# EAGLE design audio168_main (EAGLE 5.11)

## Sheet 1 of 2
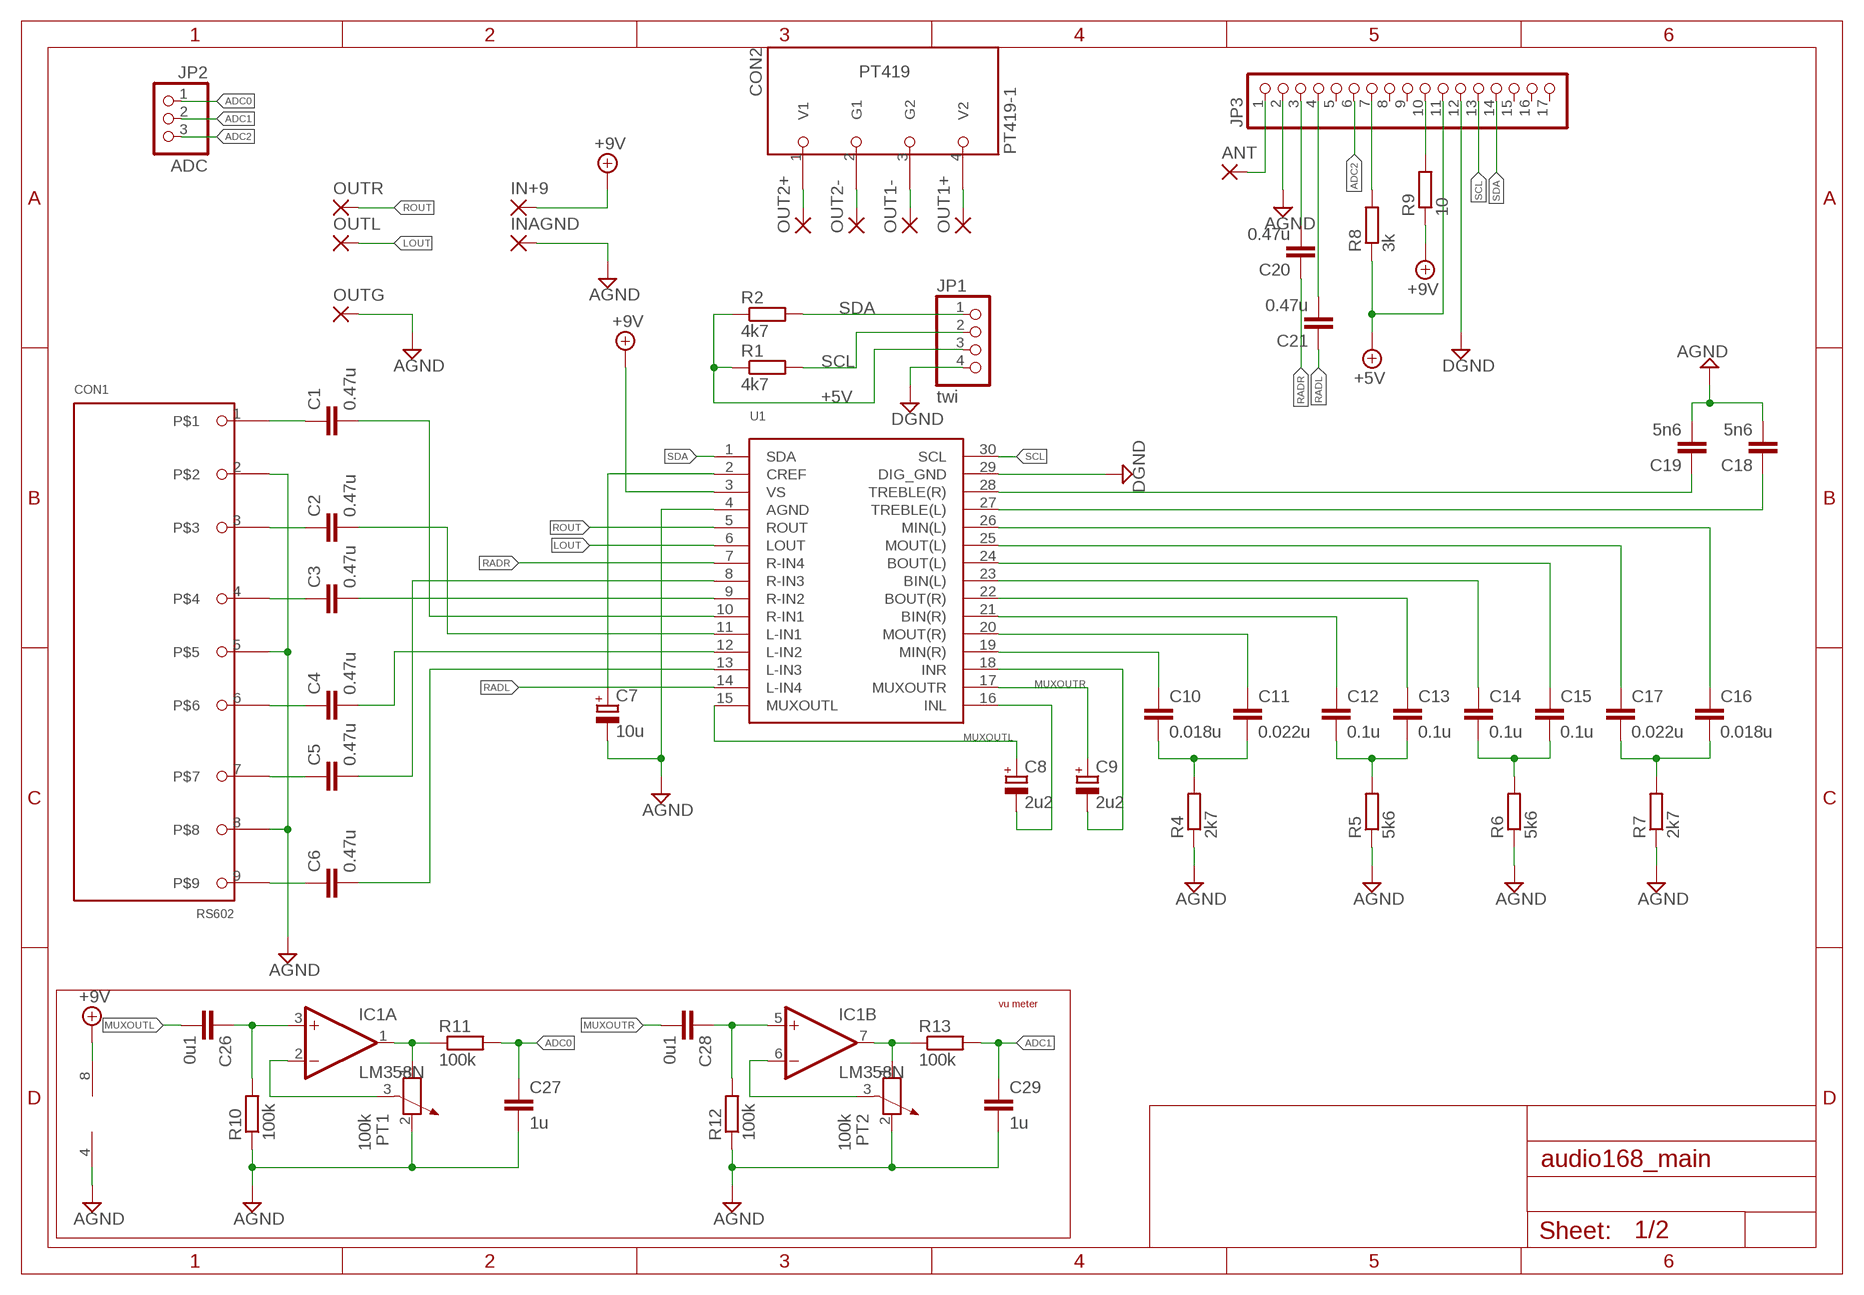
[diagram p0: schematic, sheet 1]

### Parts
ANT  2,54/0,8  [2,54/0,8]
C1  0.47u  C-EU050-055X075  [C050-055X075]
C2  0.47u  C-EU050-055X075  [C050-055X075]
C3  0.47u  C-EU050-055X075  [C050-055X075]
C4  0.47u  C-EU050-055X075  [C050-055X075]
C5  0.47u  C-EU050-055X075  [C050-055X075]
C6  0.47u  C-EU050-055X075  [C050-055X075]
C7  10u  CPOL-EUE5-4  [E5-4]
C8  2u2  CPOL-EUE2.5-6  [E2,5-6]
C9  2u2  CPOL-EUE2.5-6  [E2,5-6]
C10  0.018u  C-EU050-055X075  [C050-055X075]
C11  0.022u  C-EU050-055X075  [C050-055X075]
C12  0.1u  C-EU050-055X075  [C050-055X075]
C13  0.1u  C-EU050-055X075  [C050-055X075]
C14  0.1u  C-EU050-055X075  [C050-055X075]
C15  0.1u  C-EU050-055X075  [C050-055X075]
C16  0.018u  C-EU050-055X075  [C050-055X075]
C17  0.022u  C-EU050-055X075  [C050-055X075]
C18  5n6  C-EU050-055X075  [C050-055X075]
C19  5n6  C-EU050-055X075  [C050-055X075]
C20  0.47u  C-EU050-055X075  [C050-055X075]
C21  0.47u  C-EU050-055X075  [C050-055X075]
C26  0u1  C-EU050-055X075  [C050-055X075]
C27  1u  C-EU050-055X075  [C050-055X075]
C28  0u1  C-EU050-055X075  [C050-055X075]
C29  1u  C-EU050-055X075  [C050-055X075]
CON1  RS602  [RS602]
CON2  PT419-1  [PT419]
IC1  LM358N  [DIL08]
IN+9  2,54/0,8  [2,54/0,8]
INAGND  2,54/0,8  [2,54/0,8]
JP1  twi  PINHD-1X4  [1X04]
JP2  ADC  PINHD-1X3  [1X03]
JP3  PINHD-1X17  [1X17]
OUT1+  2,54/0,8  [2,54/0,8]
OUT1-  2,54/0,8  [2,54/0,8]
OUT2+  2,54/0,8  [2,54/0,8]
OUT2-  2,54/0,8  [2,54/0,8]
OUTG  2,54/0,8  [2,54/0,8]
OUTL  2,54/0,8  [2,54/0,8]
OUTR  2,54/0,8  [2,54/0,8]
PT1  100k  POTE  [PT-20]
PT2  100k  POTE  [PT-20]
R1  4k7  R-EU_0207/7  [0207/7]
R2  4k7  R-EU_0207/7  [0207/7]
R4  2k7  R-EU_0207/7  [0207/7]
R5  5k6  R-EU_0207/7  [0207/7]
R6  5k6  R-EU_0207/7  [0207/7]
R7  2k7  R-EU_0207/7  [0207/7]
R8  3k  R-EU_M1206  [M1206]
R9  10  R-EU_M1206  [M1206]
R10  100k  R-EU_M1206  [M1206]
R11  100k  R-EU_M1206  [M1206]
R12  100k  R-EU_M1206  [M1206]
R13  100k  R-EU_M1206  [M1206]
U1  TDA7439  [SDIP]

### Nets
+5V: JP1.3 JP3.11 R1.1 R2.1 R8.1
+9V: IC1.8(P:V+) IN+9.1(P) R9.1 U1.3(VS)
ADC0: C27.1 JP2.1 R11.2
ADC1: C29.1 JP2.2 R13.2
ADC2: JP2.3 JP3.6
AGND: C7.- C18.2 C19.2 C27.2 C29.2 CON1.2 CON1.5 CON1.8 IC1.4(P:V-) INAGND.1(P) JP3.2 OUTG.1(P) PT1.2 PT2.2 R4.1 R5.1 R6.1 R7.1 R10.1 R12.1 U1.4(AGND)
DGND: JP1.4 JP3.12 U1.29(DIG_GND)
LOUT: OUTL.1(P) U1.6(LOUT)
MUXOUTL: C8.+ C26.2 U1.15(MUXOUTL)
MUXOUTR: C9.+ C28.2 U1.17(MUXOUTR)
N$17: C1.2 U1.10(R-IN1)
N$18: C1.1 CON1.1
N$19: C2.1 CON1.3
N$20: C3.1 CON1.4
N$21: C4.1 CON1.6
N$22: C5.1 CON1.7
N$23: C6.1 CON1.9
N$24: C2.2 U1.11(L-IN1)
N$25: C3.2 U1.9(R-IN2)
N$26: C4.2 U1.12(L-IN2)
N$27: C6.2 U1.13(L-IN3)
N$28: C5.2 U1.8(R-IN3)
N$30: ANT.1(P) JP3.1
N$31: C7.+ U1.2(CREF)
N$33: C10.1 U1.19(MIN(R))
N$34: C11.1 U1.20(MOUT(R))
N$35: C8.- U1.16(INL)
N$36: C10.2 C11.2 R4.2
N$37: C9.- U1.18(INR)
N$38: C17.1 U1.25(MOUT(L))
N$39: C12.1 U1.21(BIN(R))
N$40: C12.2 C13.2 R5.2
N$41: C13.1 U1.22(BOUT(R))
N$42: C16.2 C17.2 R7.2
N$43: C14.2 C15.2 R6.2
N$44: C16.1 U1.26(MIN(L))
N$45: C14.1 U1.23(BIN(L))
N$46: C15.1 U1.24(BOUT(L))
N$47: C20.2 JP3.3
N$48: C18.1 U1.27(TREBLE(L))
N$49: C19.1 U1.28(TREBLE(R))
N$50: IC1.2(A:-IN) PT1.3
N$51: C21.2 JP3.4
N$52: JP3.7 R8.2
N$54: JP3.10 R9.2
N$55: C26.1 IC1.3(A:+IN) R10.2
N$56: IC1.6(B:-IN) PT2.3
N$57: C28.1 IC1.5(B:+IN) R12.2
N$58: IC1.1(A:OUT) PT1.1 R11.1
N$59: IC1.7(B:OUT) PT2.1 R13.1
N$61: CON2.1(V1) OUT2+.1(P)
N$62: CON2.2(G1) OUT2-.1(P)
N$63: CON2.3(G2) OUT1-.1(P)
N$64: CON2.4(V2) OUT1+.1(P)
RADL: C21.1 U1.14(L-IN4)
RADR: C20.1 U1.7(R-IN4)
ROUT: OUTR.1(P) U1.5(ROUT)
SCL: JP1.2 JP3.13 R1.2 U1.30(SCL)
SDA: JP1.1 JP3.14 R2.2 U1.1(SDA)
Unconnected: JP3.5 JP3.8 JP3.9 JP3.15 JP3.16 JP3.17

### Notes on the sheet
- vu meter

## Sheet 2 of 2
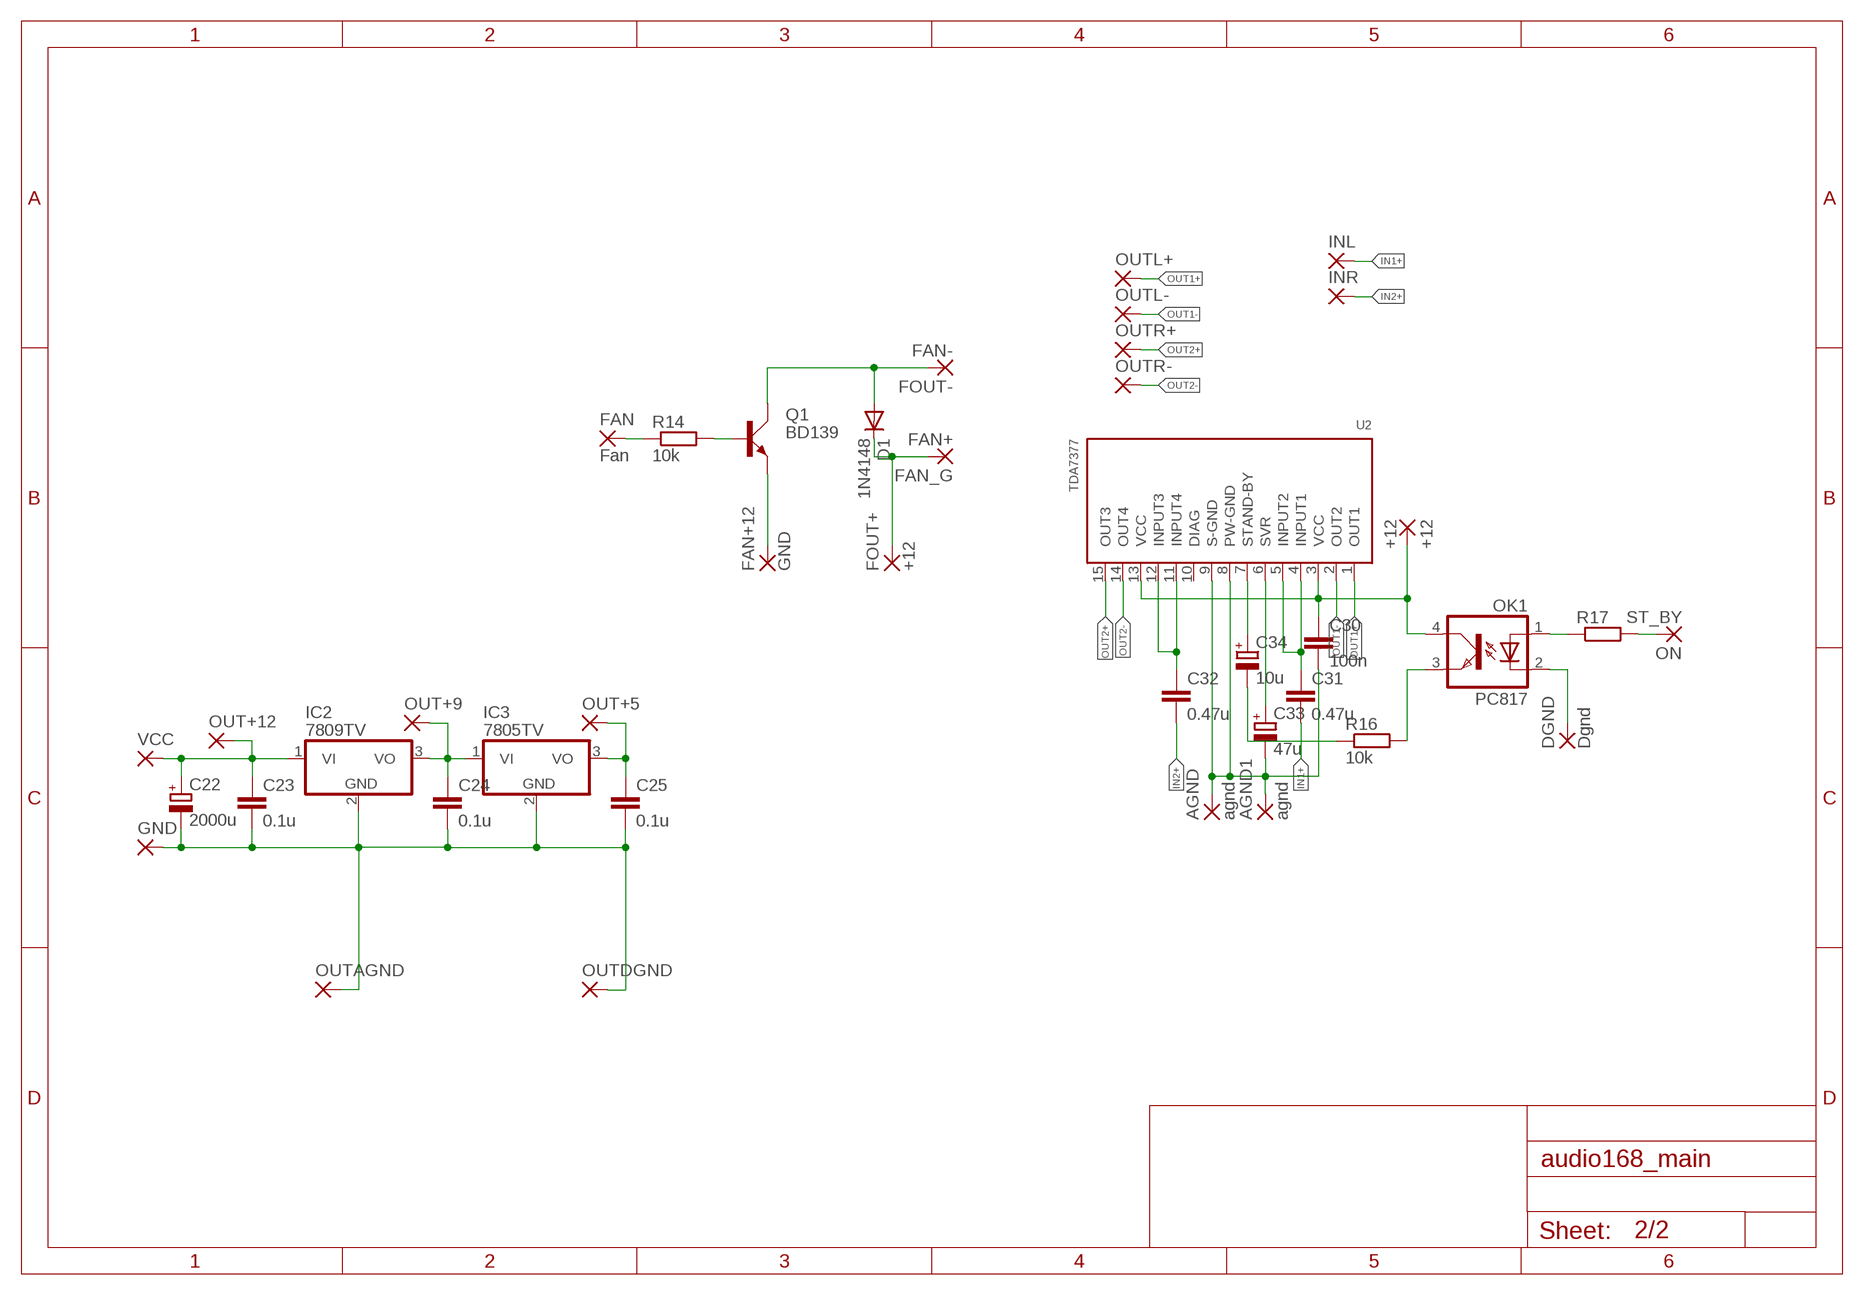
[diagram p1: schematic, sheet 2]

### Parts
+12  +12  2,54/1,1  [2,54/1,1]
AGND  agnd  2,54/1,1  [2,54/1,1]
AGND1  agnd  2,54/1,1  [2,54/1,1]
C22  2000u  CPOL-EUE7.5-18  [E7,5-18]
C23  0.1u  C-EU050-075X075  [C050-075X075]
C24  0.1u  C-EU050-075X075  [C050-075X075]
C25  0.1u  C-EU050-075X075  [C050-075X075]
C30  100n  C-EU050-055X075  [C050-055X075]
C31  0.47u  C-EU050-055X075  [C050-055X075]
C32  0.47u  C-EU050-055X075  [C050-055X075]
C33  47u  CPOL-EUE2.5-5  [E2,5-5]
C34  10u  CPOL-EUE2.5-5  [E2,5-5]
D1  1N4148  1N4148DO35-7  [DO35-7]
DGND  Dgnd  2,54/1,1  [2,54/1,1]
FAN  Fan  2,54/1,1  [2,54/1,1]
FAN+12  GND  2,54/1,1  [2,54/1,1]
FAN_G  FAN+  2,54/1,1  [2,54/1,1]
FOUT+  +12  2,54/1,1  [2,54/1,1]
FOUT-  FAN-  2,54/1,1  [2,54/1,1]
GND  2,54/1,0  [2,54/1,0]
IC2  7809TV  7805TV  [TO220V]
IC3  7805TV  [TO220V]
INL  2,54/1,1  [2,54/1,1]
INR  2,54/1,1  [2,54/1,1]
OK1  PC817  [DIL04]
ON  ST_BY  2,54/1,1  [2,54/1,1]
OUT+5  2,54/1,0  [2,54/1,0]
OUT+9  2,54/1,0  [2,54/1,0]
OUT+12  2,54/1,0  [2,54/1,0]
OUTAGND  2,54/1,0  [2,54/1,0]
OUTDGND  2,54/1,0  [2,54/1,0]
OUTL+  2,54/1,1  [2,54/1,1]
OUTL-  2,54/1,1  [2,54/1,1]
OUTR+  2,54/1,1  [2,54/1,1]
OUTR-  2,54/1,1  [2,54/1,1]
Q1  BD139  [TO126AV]
R14  10k  R-EU_0207/7  [0207/7]
R16  10k  R-EU_0207/7  [0207/7]
R17  R-EU_0207/7  [0207/7]
U2  TDA7377  [MULTIWATT-15]
VCC  2,54/1,0  [2,54/1,0]

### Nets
IN1+: C31.2 INL.1(P)
IN2+: C32.2 INR.1(P)
N$1: C22.+ C23.1 IC2.1(VI) OUT+12.1(P) VCC.1(P)
N$2: C22.- C23.2 C24.2 C25.2 GND.1(P) IC2.2(GND) IC3.2(GND) OUTAGND.1(P) OUTDGND.1(P)
N$3: C24.1 IC2.3(VO) IC3.1(VI) OUT+9.1(P)
N$4: OK1.1(A) R17.1
N$5: C25.1 IC3.3(VO) OUT+5.1(P)
N$6: C32.1 U2.11(INPUT4) U2.12(INPUT3)
N$9: C31.1 U2.4(INPUT1) U2.5(INPUT2)
N$10: +12.1(P) C30.1 OK1.4(COL) U2.3(VCC) U2.13(VCC)
N$11: AGND1.1(P) AGND.1(P) C30.2 C33.- U2.8(PW-GND) U2.9(S-GND)
N$12: C33.+ U2.6(SVR)
N$13: C34.+ U2.7(STAND-BY)
N$14: C34.- R16.1
N$15: OK1.3(EMIT) R16.2
N$16: ON.1(P) R17.2
N$29: DGND.1(P) OK1.2(C)
N$60: FAN.1(P) R14.1
N$65: Q1.B R14.2
N$66: FAN+12.1(P) Q1.E
N$67: D1.A FOUT-.1(P) Q1.C
N$68: D1.C FAN_G.1(P) FOUT+.1(P)
OUT1+: OUTL+.1(P) U2.1(OUT1)
OUT1-: OUTL-.1(P) U2.2(OUT2)
OUT2+: OUTR+.1(P) U2.15(OUT3)
OUT2-: OUTR-.1(P) U2.14(OUT4)
Unconnected: U2.10(DIAG)

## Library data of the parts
+12 AGND AGND1 DGND FAN FAN+12 FAN_G FOUT+ FOUT- INL INR ON OUTL+ OUTL- OUTR+ OUTR- = wirepad:2,54/1,1: THROUGH-HOLE PAD
ANT IN+9 INAGND OUT1+ OUT1- OUT2+ OUT2- OUTG OUTL OUTR = wirepad:2,54/0,8: THROUGH-HOLE PAD
C1-C6 C10-C21 C23-C32 = rcl:C-EU: CAPACITOR, European symbol
C7-C9 C22 C33 C34 = rcl:CPOL-EU: POLARIZED CAPACITOR, European symbol
CON1 = ds:RS602
CON2 = ds:PT419-1
D1 = diode:1N4148: DIODE
GND OUT+5 OUT+9 OUT+12 OUTAGND OUTDGND VCC = wirepad:2,54/1,0: THROUGH-HOLE PAD
IC1 = linear:LM358: OP AMP also LM158; LM258; LM2904 Source: http://cache.national.com/ds/LM/LM158.pdf
IC2 IC3 = linear:78*: Positive VOLTAGE REGULATOR Source: http://cache.national.com/ds/LM/LM78L05.pdf http://www.fairchildsemi.com/ds/LM/LM7805.pdf
JP1 = pinhead:PINHD-1X4: PIN HEADER
JP2 = pinhead:PINHD-1X3: PIN HEADER
JP3 = pinhead:PINHD-1X17: PIN HEADER
OK1 = optocoupler:PC817: SHARP OPTO COUPLER; MPN: PC817X4J000F; OC_FARNELL: 9707727; OC_NEWARK: 97K7059
PT1 PT2 = ds:POTE
Q1 = transistor-power:BD139: NPN TRANSISTOR
R1 R2 R4-R14 R16 R17 = rcl:R-EU_: RESISTOR, European symbol
U1 = ds:TDA7439
U2 = ds:TDA7377

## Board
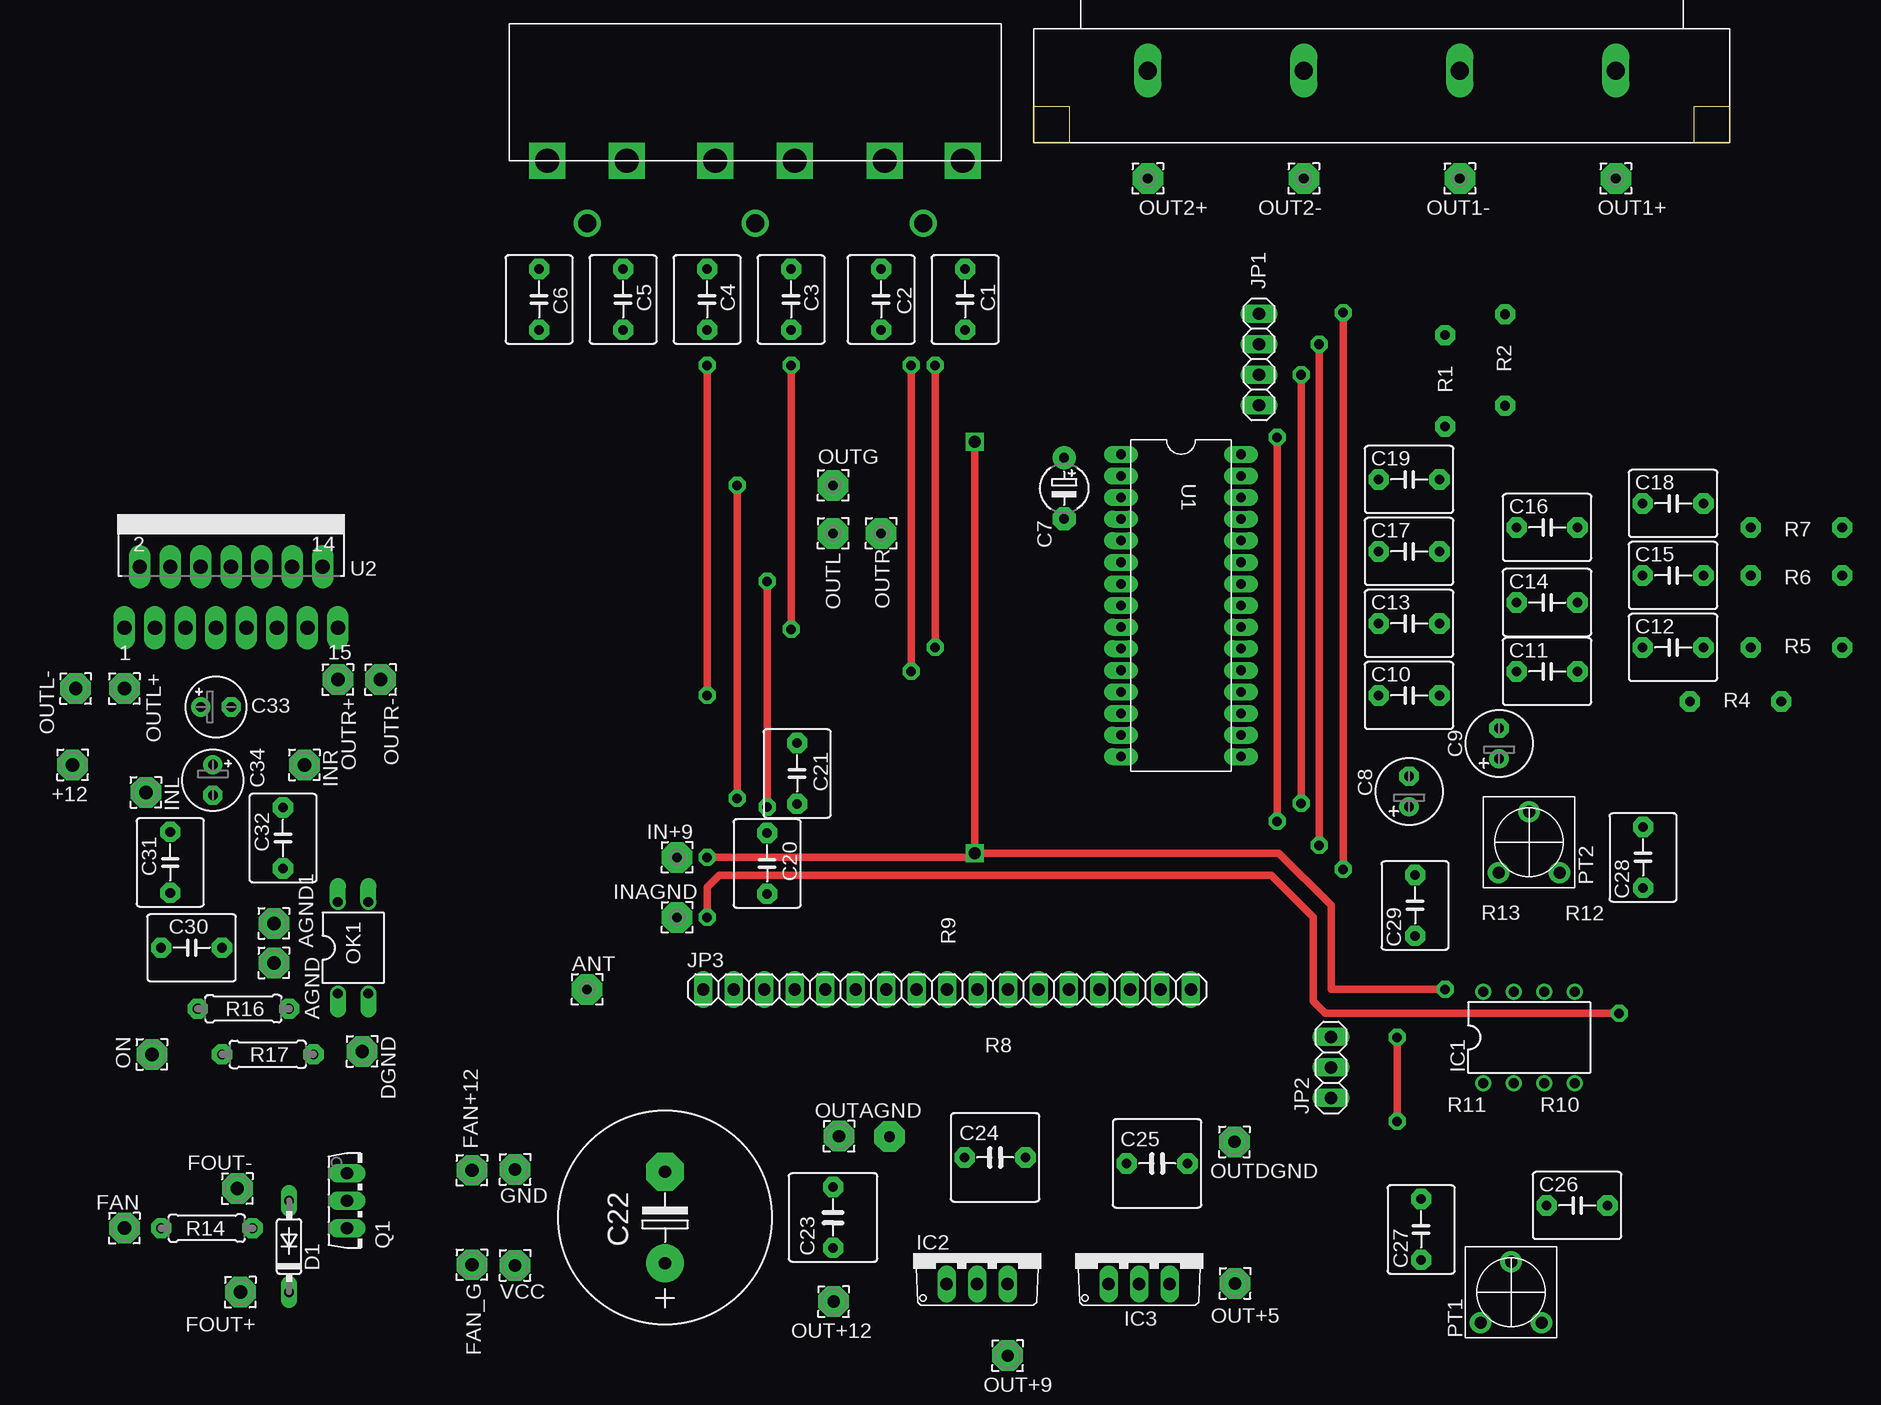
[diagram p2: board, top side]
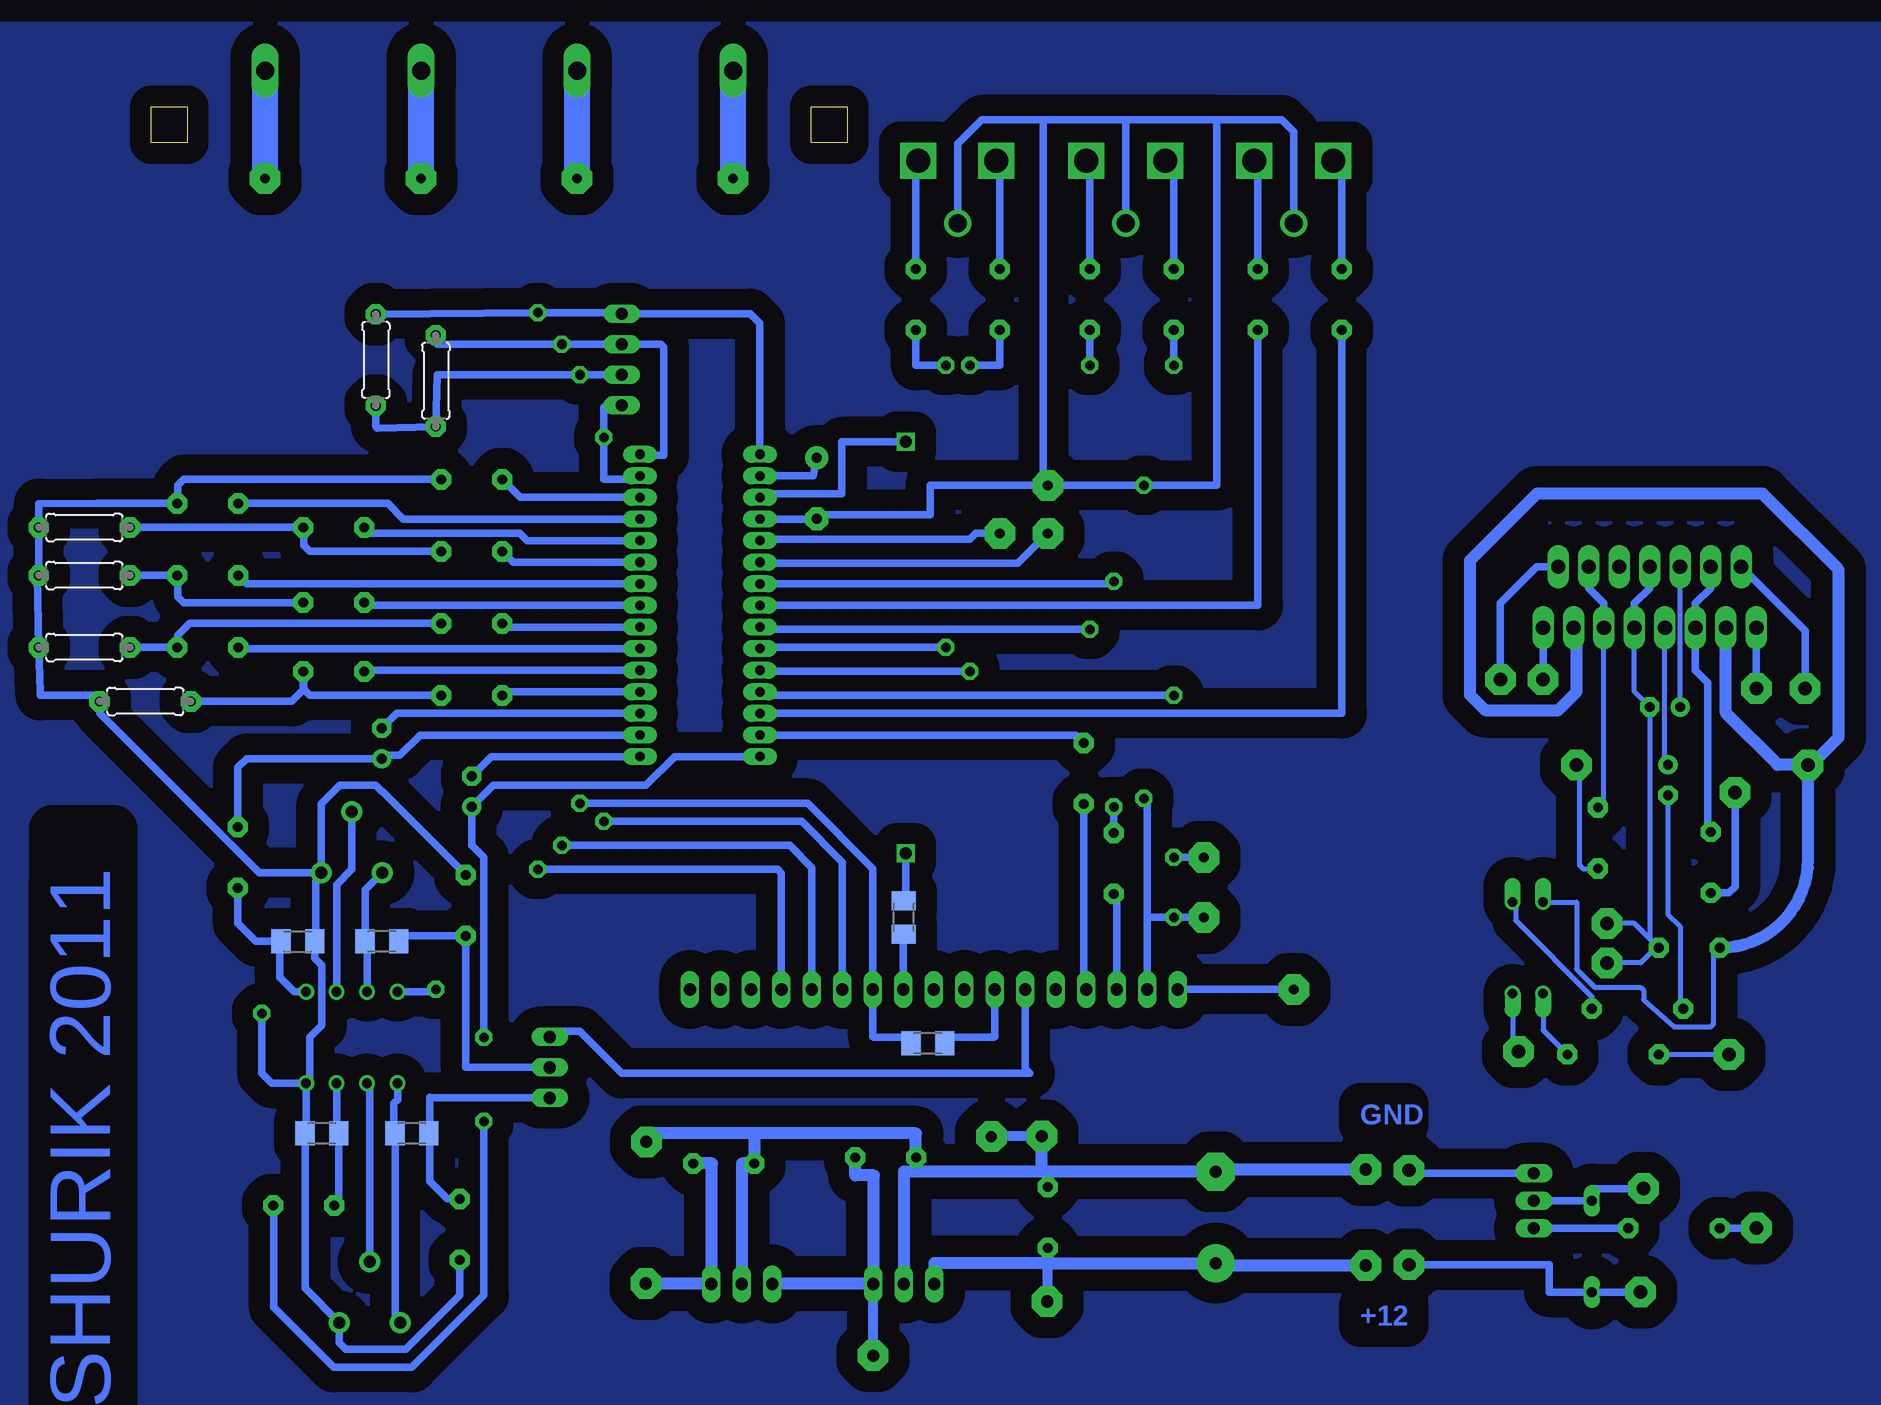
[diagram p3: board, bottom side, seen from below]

Size 58 x 3 mm. Coordinates in mm from the lower left corner, seen from the top.
Copper layers (1*16): Top 0.035mm / dielectric 1.5mm / Bottom 0.035mm
Design rules "default": minimum track width 10mil, minimum drill 24mil, track to track 8mil, track to pad 8mil, pad to pad 8mil, via to via 8mil, smd to smd 8mil, copper to edge 40mil, drill to drill 8mil, minimum pad ring 10mil, minimum via ring 8mil, stop-mask expansion 4mil, vias tented up to drill 0mil, thermal gap 10mil
tKeepout: area -87.5,-30.5 to -45.5,9.5
bRestrict: area 61.1,-105.5 to 66.2,-57.2

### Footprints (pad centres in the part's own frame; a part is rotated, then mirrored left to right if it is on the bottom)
2,54/1,1 = drill 1.118 pad 2.54 octagon: 1 0,0
2,54/0,8 = drill 0.813 pad 2.54 octagon: 1 0,0
C050-055X075 = drill 0.813 pad 1.676 octagon: 1 -2.54,0; 2 2.54,0
E5-4 = drill 0.813 pad 1.905 round: + -2.54,0 | drill 0.813 pad 1.905 octagon: - 2.54,0
E2,5-6 = drill 0.813 pad 1.6 round: + -1.27,0 | drill 0.813 pad 1.6 octagon: - 1.27,0
E7,5-18 = drill 1.016 pad 3.15 round: + -3.81,0 | drill 1.016 pad 3.15 octagon: - 3.81,0
C050-075X075 = drill 0.813 pad 1.676 octagon: 1 -2.54,0; 2 2.54,0
E2,5-5 = drill 0.813 pad 1.6 round: + -1.27,0 | drill 0.813 pad 1.6 octagon: - 1.27,0
RS602 = drill 2 square: 1 -17.3,11.4; 3 -10.8,11.4; 4 -3.3,11.4; 6 3.3,11.4; 7 10.7,11.4; 9 17.3,11.4 | drill 1.5 round: 2 -14,16.6; 5 0,16.6; 8 14,16.6
PT419 = drill 1.5 long: 1 -19.5,-3.5; 2 -6.5,-3.5; 3 6.5,-3.5; 4 19.5,-3.5
DO35-7 = drill 0.813 long: A 3.81,0; C -3.81,0
2,54/1,0 = drill 1.016 pad 2.54 octagon: 1 0,0
DIL08 = drill 0.813 pad 1.27 round: 1 -3.81,-3.81; 2 -1.27,-3.81; 3 1.27,-3.81; 4 3.81,-3.81; 5 3.81,3.81; 6 1.27,3.81; 7 -1.27,3.81; 8 -3.81,3.81
TO220V = drill 1.016 long: 1 -2.54,-2.54; 2 0,-2.54; 3 2.54,-2.54
1X04 = drill 1.016 long: 1 -3.81,0; 2 -1.27,0; 3 1.27,0; 4 3.81,0
1X03 = drill 1.016 long: 1 -2.54,0; 2 0,0; 3 2.54,0
1X17 = drill 1.016 long: 1 -20.32,0; 2 -17.78,0; 3 -15.24,0; 4 -12.7,0; 5 -10.16,0; 6 -7.62,0; 7 -5.08,0; 8 -2.54,0; 9 0,0; 10 2.54,0; 11 5.08,0; 12 7.62,0; 13 10.16,0; 14 12.7,0; 15 15.24,0; 16 17.78,0; 17 20.32,0
DIL04 = drill 0.813 offset: 1 -1.27,-3.81; 2 1.27,-3.81; 3 1.27,3.81; 4 -1.27,3.81
PT-20 = drill 1 pad 1.778 round: 1 -2.54,-1.27; 2 2.54,-1.27; 3 0,3.81
TO126AV = drill 1.016 long: B 2.286,-1.27; C 0,-1.27; E -2.286,-1.27
0207/7 = drill 0.813 pad 1.676 octagon: 1 -3.81,0; 2 3.81,0
M1206 = smd 1.6 x 2: 1 -1.4,0; 2 1.4,0
SDIP = drill 0.8 pad 1.422 long: 1 -5,12.6; 2 -5,10.8; 3 -5,9; 4 -5,7.2; 5 -5,5.4; 6 -5,3.6; 7 -5,1.8; 8 -5,0; 9 -5,-1.8; 10 -5,-3.6; 11 -5,-5.4; 12 -5,-7.2; 13 -5,-9; 14 -5,-10.8; 15 -5,-12.6; 16 5,-12.6; 17 5,-10.8; 18 5,-9; 19 5,-7.2; 20 5,-5.4; 21 5,-3.6; 22 5,-1.8; 23 5,0; 24 5,1.8; 25 5,3.6; 26 5,5.4; 27 5,7.2; 28 5,9; 29 5,10.8; 30 5,12.6
MULTIWATT-15 = drill 1.2 long: 1 -8.89,-7.62; 2 -7.62,-2.54; 3 -6.35,-7.62; 4 -5.08,-2.54; 5 -3.81,-7.62; 6 -2.54,-2.54; 7 -1.27,-7.62; 8 0,-2.54; 9 1.27,-7.62; 10 2.54,-2.54; 11 3.81,-7.62; 12 5.08,-2.54; 13 6.35,-7.62; 14 7.62,-2.54; 15 8.89,-7.62

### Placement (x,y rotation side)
+12  -80.1,-51.86 270 top  (outside the outline)
AGND  -63.33,-68.37 270 top  (outside the outline)
AGND1  -63.33,-65.07 270 top  (outside the outline)
ANT  -37.23,-70.58 0 top  (outside the outline)
C1  -5.73,-13.08 270 top  (outside the outline)
C2  -12.73,-13.08 270 top  (outside the outline)
C3  -20.23,-13.08 270 top  (outside the outline)
C4  -27.23,-13.08 270 top  (outside the outline)
C5  -34.23,-13.08 270 top  (outside the outline)
C6  -41.23,-13.08 270 top  (outside the outline)
C7  2.52,-28.82 270 top  (outside the outline)
C8  31.27,-54.08 90 top  (outside the outline)
C9  38.77,-50.08 90 top  (outside the outline)
C10  31.27,-46.08 0 top  (outside the outline)
C11  42.77,-44.08 0 top  (outside the outline)
C12  53.27,-42.08 0 top  (outside the outline)
C13  31.27,-40.08 0 top  (outside the outline)
C14  42.77,-38.33 0 top  (outside the outline)
C15  53.27,-36.08 0 top  (outside the outline)
C16  42.77,-32.08 0 top  (outside the outline)
C17  31.27,-34.08 0 top  (outside the outline)
C18  53.27,-30.08 0 top  (outside the outline)
C19  31.27,-28.08 0 top  (outside the outline)
C20  -22.23,-60.08 270 top  (outside the outline)
C21  -19.73,-52.58 270 top  (outside the outline)
C22  -30.73,-89.58 90 top  (outside the outline)
C23  -16.73,-89.58 90 top  (outside the outline)
C24  -3.23,-84.58 180 top  (outside the outline)
C25  10.27,-85.08 180 top  (outside the outline)
C26  45.27,-88.58 0 top  (outside the outline)
C27  32.27,-90.58 270 top  (outside the outline)
C28  50.77,-59.58 90 top  (outside the outline)
C29  31.77,-63.58 90 top  (outside the outline)
C30  -70.19,-67.1 0 top  (outside the outline)
C31  -71.97,-59.99 270 top  (outside the outline)
C32  -62.57,-57.96 270 top  (outside the outline)
C33  -68.16,-47.04 0 top  (outside the outline)
C34  -68.41,-53.13 270 top  (outside the outline)
CON1  -23.23,9.88 180 top  (outside the outline)
CON2  29,9.5 0 top
D1  -62.06,-92 90 top  (outside the outline)
DGND  -55.97,-75.74 270 top  (outside the outline)
DRILEGEND  [DRILEGEND]  not placed on the board
FAN  -75.78,-90.47 0 top  (outside the outline)
FAN+12  -46.82,-85.65 0 top  (outside the outline)
FAN_G  -46.82,-93.52 0 top  (outside the outline)
FOUT+  -66.13,-95.81 0 top  (outside the outline)
FOUT-  -66.38,-87.17 0 top  (outside the outline)
GND  -43.23,-85.58 0 top  (outside the outline)
IC1  41.27,-74.58 0 top  (outside the outline)
IC2  -4.73,-92.58 0 top  (outside the outline)
IC3  8.77,-92.58 0 top  (outside the outline)
IN+9  -29.73,-59.58 0 top  (outside the outline)
INAGND  -29.73,-64.58 0 top  (outside the outline)
INL  -74,-54.15 270 top  (outside the outline)
INR  -60.79,-51.86 270 top  (outside the outline)
JP1  18.77,-18.08 270 top  (outside the outline)
JP2  24.77,-77.08 90 top  (outside the outline)
JP3  -7.23,-70.58 0 top  (outside the outline)
OK1  -56.73,-67.1 0 top  (outside the outline)
ON  -73.49,-75.99 270 top  (outside the outline)
OUT1+  48.5,-3 0 top
OUT1-  35.5,-3 0 top
OUT2+  9.5,-3 0 top
OUT2-  22.5,-3 0 top
OUT+5  16.77,-95.08 0 top  (outside the outline)
OUT+9  -2.17,-101.1 0 top  (outside the outline)
OUT+12  -16.68,-96.59 0 top  (outside the outline)
OUTAGND  -16.23,-82.81 0 top  (outside the outline)
OUTDGND  16.72,-83.28 0 top  (outside the outline)
OUTG  -16.73,-28.58 0 top  (outside the outline)
OUTL  -16.73,-32.58 0 top  (outside the outline)
OUTL+  -75.78,-45.51 270 top  (outside the outline)
OUTL-  -79.84,-45.51 270 top  (outside the outline)
OUTR  -12.73,-32.58 0 top  (outside the outline)
OUTR+  -58,-44.75 270 top  (outside the outline)
OUTR-  -54.44,-44.75 270 top  (outside the outline)
PT1  39.77,-97.08 0 top  (outside the outline)
PT2  41.27,-59.58 0 top  (outside the outline)
Q1  -55.97,-88.19 270 top  (outside the outline)
R1  34.27,-19.86 90 bottom  (outside the outline)
R2  39.27,-18.12 90 bottom  (outside the outline)
R4  58.48,-46.58 0 bottom  (outside the outline)
R5  63.56,-42.08 0 bottom  (outside the outline)
R6  63.56,-36.08 0 bottom  (outside the outline)
R7  63.56,-32.08 0 bottom  (outside the outline)
R8  -6.73,-75.08 0 bottom  (outside the outline)
R9  -4.73,-64.58 270 bottom  (outside the outline)
R10  43.77,-82.58 0 bottom  (outside the outline)
R11  36.27,-82.58 0 bottom  (outside the outline)
R12  45.77,-66.58 180 bottom  (outside the outline)
R13  38.77,-66.58 0 bottom  (outside the outline)
R14  -68.92,-90.47 0 top  (outside the outline)
R16  -65.87,-72.18 0 top  (outside the outline)
R17  -63.84,-75.99 180 top  (outside the outline)
U1  12.27,-38.58 0 top  (outside the outline)
U2  -66.89,-32.81 0 top  (outside the outline)
VCC  -43.23,-93.58 0 top  (outside the outline)

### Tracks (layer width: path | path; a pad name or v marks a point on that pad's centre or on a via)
+5V  (via drill 0.8 pad 1.42)
  Top 0.61: v22.27,-55.08 v22.27,-19.35
  Bottom 0.61: R2.1 39.27,-23.66 39.13,-23.8 R1.1 34.14,-19.35 v22.27,-19.35 JP1.3 | R8.1 -4.83,-74.58 -2.23,-74.58 -2.15,-74.5 JP3.11 -2.15,-60.5 3.27,-55.08 v22.27,-55.08
+9V  (via drill 0.8 pad 1.42, 1 pad 1.27)
  Top 0.61: v34.27,-70.58 24.77,-70.58 24.77,-63.58 20.42,-59.23 v-4.91,-59.23 | v-4.91,-59.23 v-4.91,-24.94 | v-27.23,-59.58 -4.91,-59.58 v-4.91,-59.23
  Bottom 0.61: IC1.8 34.46,-70.77 v34.27,-70.58 | IN+9.1 v-27.23,-59.58 | 7.27,-29.51 U1.3 7.27,-29.26 0.42,-29.26 0.42,-24.94 v-4.91,-24.94 | R9.1 -4.73,-63.04 -4.91,-63.04 v-4.91,-59.23
ADC0
  Bottom 0.61: C27.1 33.31,-88.04 34.77,-86.58 34.77,-82.68 R11.2 34.77,-82.48 34.77,-79.58 34.31,-79.62 JP2.1
ADC1
  Bottom 0.61: R13.2 36.91,-66.12 C29.1 31.77,-77.08 JP2.2
ADC2
  Bottom 0.61: JP3.6 -14.85,-77.2 -15.23,-77.58 18.77,-77.58 22.27,-74.08 24.31,-74.08 | 24.31,-74.08 25.27,-74.08 | 24.31,-74.08 JP2.3
AGND  (via drill 0.8 pad 1.42)
  Top 0.61: v-24.73,-54.66 v-24.73,-28.58 | v48.77,-72.58 24.27,-72.58 23.27,-71.58 23.27,-64.58 19.77,-61.08 -26.23,-61.08 -27.23,-62.08 v-27.23,-64.58
  Bottom 0.61: CON1.2 -9.23,-0.12 -11.23,1.88 -16.34,1.88 | -23.23,1.88 -16.34,1.88 | -23.23,1.88 CON1.5 | CON1.8 -37.23,0.88 -36.23,1.88 -30.82,1.88 | -30.82,1.88 -23.23,1.88 | C19.2 55.27,-28.08 55.77,-28.58 55.77,-30.04 C18.2 61.77,-30.08 62.52,-30.07 67.35,-30.09 R7.1 67.35,-32.18 67.35,-35.98 R6.1 67.48,-36.08 67.48,-36.12 R5.1 67.22,-45.77 67.22,-46.08 62.17,-46.08 | 62.17,-46.08 R4.1 | PT2.2 43.81,-61.12 44.27,-61.58 44.27,-66.48 R12.1 44.37,-67.98 43.77,-68.58 43.77,-73.58 44.77,-74.58 44.77,-78.08 IC1.4 | PT2.2 49,-60.85 62.27,-47.58 62.27,-46.18 62.17,-46.08 | PT2.2 43.81,-55.12 42.27,-53.58 39.27,-53.58 38.77,-54.08 38.73,-54.08 C29.2 | IC1.4 45.08,-82.49 R10.1 45.17,-95.49 PT1.2 42.31,-100.04 41.77,-100.58 36.77,-100.58 32.27,-96.08 C27.2 | OUTG.1 -16.23,-28.08 | -25.01,-64.58 -25.01,-54.94 v-24.73,-54.66 -24.73,-54.94 | OUTG.1 v-24.73,-28.58 -30.82,-28.58 -30.82,1.88 | INAGND.1 v-27.23,-64.58 -25.01,-64.58 | IC1.4 47.96,-78.39 48.77,-77.58 v48.77,-72.58 | JP3.2 -25.01,-64.58 | U1.4 2.8,-31.38 C7.- 2.27,-31.04 -6.94,-31.04 -6.94,-28.58 OUTG.1 | -16.34,1.88 -16.34,-28.75
DGND  (via drill 0.8 pad 1.42)
  Top 0.61: v20.27,-56.58 v20.27,-24.58
  Bottom 0.61: JP1.4 20.08,-21.89 20.27,-22.08 v20.27,-24.58 20.27,-28.08 17.57,-28.08 U1.29 | JP3.12 0.39,-59.96 3.77,-56.58 v20.27,-56.58
IN1+
  Bottom 0.61: INL.1 -74,-62.02 -73.49,-62.53 C31.2
IN2+
  Bottom 0.406: C32.2 -61.3,-60.5 -61.05,-60.25 -61.05,-52.12 INR.1
LOUT
  Bottom 0.61: OUTL.1 -14.23,-35.08 7.17,-35.08 U1.6
MUXOUTL  (via drill 0.8 pad 1.42)
  Top 0.61: v30.27,-81.58 v30.27,-74.58
  Bottom 0.61: U1.15 14.37,-51.18 16.77,-53.58 29.5,-53.58 C8.+ 31.27,-58.58 30.27,-59.58 v30.27,-74.58 | v30.27,-81.58 30.27,-96.08 36.27,-102.08 42.77,-102.08 47.77,-97.08 47.77,-88.62 C26.2
MUXOUTR
  Bottom 0.61: U1.17 35.57,-49.38 37.27,-51.08 38.5,-51.08 C9.+ 50.04,-51.35 50.77,-52.08 C28.2
N$1
  Bottom 0.813: OUT+12.1 -16.73,-96.59 -16.73,-93.01
  Bottom 1.016: VCC.1 -30.73,-93.58 C22.+ -16.73,-93.39 | -16.73,-93.39 -16.73,-93.01 C23.1 | -16.73,-93.39 -7.27,-93.39 IC2.1
N$2  (via drill 0.9 pad 2.54)
  Bottom 0.813: OUTAGND.1 -12.02,-82.81 v-12.02,-82.85 | 16.27,-82.58 16.72,-82.58 OUTDGND.1
  Bottom 1.016: GND.1 -30.73,-85.58 C22.- -16.73,-85.77 | -16.73,-85.77 C23.2 | -16.73,-85.77 -16.23,-85.77 | -16.23,-85.77 OUTAGND.1 | -16.23,-85.77 -5.77,-85.77 | -5.77,-85.77 C24.2 | -5.77,-85.77 -5.73,-85.77 | IC2.2 -4.73,-85.77 -5.73,-85.77 | -5.73,-85.77 -5.73,-82.58 7.73,-82.58 | 7.73,-82.58 C25.2 8.77,-85.08 IC3.2 | 7.73,-82.58 16.27,-82.58
N$3
  Bottom 0.813: -2.23,-95.12 -2.17,-95.12 OUT+9.1
  Bottom 1.016: IC3.1 IC2.3 -2.23,-95.12 -2.23,-86.08 -0.69,-86.08 C24.1
N$4
  Bottom 0.406: OK1.1 -58,-73.96 R17.1
N$5
  Bottom 1.016: C25.1 11.27,-85.08 11.27,-95.12 IC3.3 16.77,-95.12 OUT+5.1
N$6
  Bottom 0.406: U2.11 -63.08,-54.91 C32.1
  Bottom 0.61: U2.12 -61.81,-37.13 -63.08,-38.4 U2.11
N$7
  pour Bottom (isolate 1.778): -88.48,9.86 70.78,9.86 70.78,-109.01 -88.48,-109.01
N$9
  Bottom 0.61: U2.4 -71.97,-37.13 -70.7,-38.4 U2.5 -70.7,-43.99 -71.71,-45.01 -71.71,-57.2 C31.1
N$10
  Bottom 0.406: OK1.4 -60.79,-63.29 -60.79,-68.88 -62.32,-70.41 -66.13,-70.41 -66.38,-70.66 -66.38,-71.42 -68.92,-73.71 -71.97,-73.71 -72.22,-73.45 -72.22,-67.61 C30.1
  Bottom 1.016: U2.3 -73.24,-47.55 -77.56,-51.86 +12.1 | +12.1 -80.35,-51.86 -82.64,-49.58 -82.64,-35.61 -76.29,-29.26 -57.49,-29.26 -51.9,-34.85 -51.9,-46.02 -53.17,-47.29 -59.27,-47.29 -60.79,-45.77 -60.79,-40.69 U2.13 | +12.1 -80.1,-59.74 arc90 C30.1
N$11
  Bottom 0.406: U2.9 -65.62,-45.77 C33.- -66.89,-66.34 C30.2 | AGND1.1 -65.62,-65.07 C30.2 | C30.2 -67.4,-67.1 -66.13,-68.37 AGND.1
  Bottom 0.61: U2.8 -66.89,-37.13 -65.62,-38.4 U2.9
N$12
  Bottom 0.406: C33.+ U2.6
N$13
  Bottom 0.406: U2.7 -68.16,-51.61 C34.+
N$14
  Bottom 0.406: C34.- -68.41,-64.31 -69.43,-65.33 -69.43,-71.93 R16.1
N$15
  Bottom 0.406: R16.2 -62.06,-71.17 -55.71,-64.82 -55.71,-63.55 OK1.3
N$16
  Bottom 0.406: R17.2 ON.1
N$17  (via drill 0.8 pad 1.42)
  Top 0.61: v-8.23,-42.08 v-8.23,-18.58
  Bottom 0.61: C1.2 -5.73,-18.58 v-8.23,-18.58 | v-8.23,-42.08 7.17,-42.08 U1.10
N$18
  Bottom 0.61: C1.1 -5.73,-1.72 CON1.1
N$19
  Bottom 0.61: C2.1 -12.73,-1.82 CON1.3
N$20
  Bottom 0.61: C3.1 -20.23,-1.82 CON1.4
N$21
  Bottom 0.61: C4.1 -27.23,-2.22 CON1.6
N$22
  Bottom 0.61: C5.1 -34.23,-1.82 CON1.7
N$23
  Bottom 0.61: C6.1 -41.23,-2.22 CON1.9
N$24  (via drill 0.8 pad 1.42)
  Top 0.61: v-10.23,-44.08 v-10.23,-18.58
  Bottom 0.61: C2.2 -12.73,-18.58 v-10.23,-18.58 | v-10.23,-44.08 6.87,-44.08 U1.11
N$25  (via drill 0.8 pad 1.42)
  Top 0.61: v-20.23,-40.58 v-20.23,-18.58
  Bottom 0.61: v-20.23,-40.58 7.07,-40.58 U1.9 | v-20.23,-18.58 C3.2
N$26  (via drill 0.8 pad 1.42)
  Top 0.61: v-27.23,-46.08 v-27.23,-18.58
  Bottom 0.61: v-27.23,-46.08 6.97,-46.08 U1.12 | v-27.23,-18.58 C4.2
N$27
  Bottom 0.61: U1.13 -41.23,-47.58 C6.2
N$28
  Bottom 0.61: U1.8 -34.23,-38.58 C5.2
N$29
  Bottom 0.406: OK1.2 -55.46,-75.23 DGND.1
N$30
  Bottom 0.61: ANT.1 JP3.1
N$31
  Bottom 0.61: U1.2 2.8,-27.78 C7.+
N$33
  Bottom 0.61: U1.19 28.43,-45.78 C10.1
N$34
  Bottom 0.61: U1.20 40.13,-43.98 C11.1
N$35
  Bottom 0.61: U1.16 29.64,-51.18 C8.-
N$36
  Bottom 0.61: C10.2 44.77,-46.08 45.27,-45.58 45.27,-44.12 C11.2 45.31,-45.62 46.27,-46.58 R4.2
N$37
  Bottom 0.61: U1.18 37.54,-47.58 C9.-
N$38
  Bottom 0.61: U1.25 27.83,-34.98 C17.1
N$39
  Bottom 0.61: U1.21 50.63,-42.18 C12.1
N$40
  Bottom 0.61: C13.2 54.77,-40.08 55.77,-41.08 55.77,-42.04 C12.2 R5.2
N$41
  Bottom 0.61: U1.22 28.43,-40.38 C13.1
N$42
  Bottom 0.61: C17.2 44.77,-34.08 45.27,-33.58 45.27,-32.12 C16.2 R7.2
N$43
  Bottom 0.61: C14.2 55.27,-38.33 55.77,-37.83 55.77,-36.12 C15.2 R6.2
N$44
  Bottom 0.61: U1.26 26.67,-33.18 27.27,-32.58 39.73,-32.58 C16.1
N$45
  Bottom 0.61: U1.23 39.73,-38.58 C14.1
N$46
  Bottom 0.61: U1.24 50.03,-36.78 C15.1
N$47
  Bottom 0.61: JP3.3 -22.47,-62.86 C20.2
N$48
  Bottom 0.61: U1.27 36.97,-31.38 38.27,-30.08 C18.1
N$49
  Bottom 0.61: U1.28 27.23,-29.58 C19.1
N$50
  Bottom 0.61: PT1.3 39.77,-78.62 IC1.2
N$51
  Bottom 0.61: C21.2 -19.73,-70.38 JP3.4
N$52
  Bottom 0.61: JP3.7 -12.31,-74.5 -12.23,-74.58 -8.63,-74.58 R8.2
N$54
  Bottom 0.61: JP3.10 -4.69,-66.02 R9.2
N$55
  Bottom 0.61: IC1.3 42.54,-82.41 R10.2 42.37,-88.22 C26.1
N$56
  Bottom 0.61: IC1.6 42.54,-61.85 41.27,-60.58 PT2.3
N$57
  Bottom 0.61: IC1.5 46.08,-70.77 47.27,-69.58 47.27,-66.68 R12.2 49.27,-66.58 50.77,-65.08 C28.1
N$58
  Bottom 0.61: IC1.1 37.46,-79.77 37.77,-80.08 37.77,-82.48 R11.1 37.67,-97.91 PT1.1
N$59
  Bottom 0.61: IC1.7 40,-66.75 R13.1 40.17,-62.29 PT2.1
N$60
  Bottom 0.61: R14.1 FAN.1
N$61
  Bottom 2.184: OUT2+.1 CON2.1
N$62
  Bottom 2.184: OUT2-.1 CON2.2
N$63
  Bottom 2.184: OUT1-.1 CON2.3
N$64
  Bottom 2.184: OUT1+.1 CON2.4
N$65
  Bottom 0.61: Q1.B R14.2
N$66
  Bottom 0.61: Q1.E -46.82,-85.9 FAN+12.1
N$67
  Bottom 0.61: FOUT-.1 -62.06,-87.17 D1.A Q1.C
N$68
  Bottom 0.61: FOUT+.1 D1.C -58.51,-95.81 -58.51,-93.52 FAN_G.1
OUT1+
  Bottom 0.61: OUTL+.1 U2.1
OUT1-
  Bottom 0.61: OUTL-.1 -79.84,-40.69 U2.2
OUT2+
  Bottom 0.61: OUTR+.1 U2.15
OUT2-
  Bottom 0.61: U2.14 -57.49,-35.35 -54.44,-38.4 OUTR-.1
RADL
  Bottom 0.61: U1.14 -19.07,-49.38 C21.1
RADR  (via drill 0.8 pad 1.42)
  Top 0.61: v-22.23,-55.37 v-22.23,-36.58
  Bottom 0.61: C20.1 v-22.23,-55.37 | U1.7 -22.03,-36.78 v-22.23,-36.58
ROUT
  Bottom 0.61: OUTR.1 -10.73,-32.58 -10.23,-33.08 7.17,-33.08 U1.5
SCL  (via drill 0.8 pad 1.42)
  Top 0.61: v23.77,-58.58 v23.77,-16.81
  Bottom 0.61: U1.30 17.17,-26.08 15.27,-26.08 15.27,-17.08 15.54,-16.81 JP1.2 v23.77,-16.81 34.14,-16.81 R1.2 | JP3.13 2.93,-60.42 4.77,-58.58 v23.77,-58.58
SDA  (via drill 0.8 pad 1.42)
  Top 0.61: v25.77,-60.58 v25.77,-14.18
  Bottom 0.61: U1.1 7.27,-15.08 8.08,-14.27 JP1.1 18.86,-14.18 v25.77,-14.18 R2.2 | JP3.14 5.47,-60.88 5.77,-60.58 v25.77,-60.58

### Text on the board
Bottom: GND | +12 | SHURIK 2011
